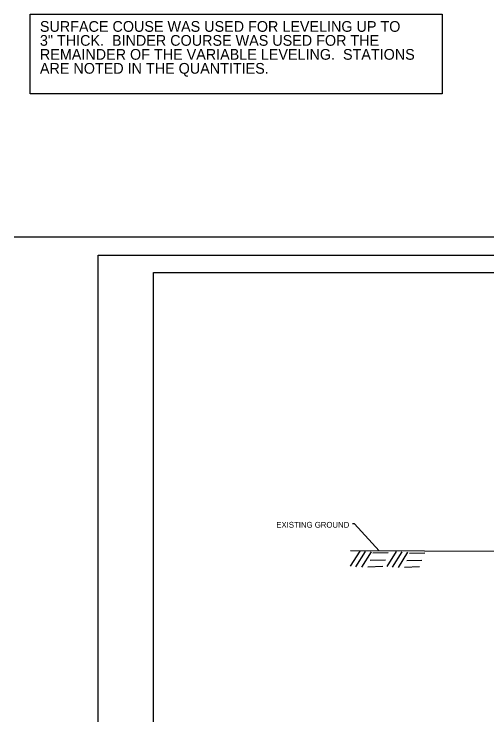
# Model space of a CAD drawing. Extents: x 1373719 to 1374161, y 379835 to 380167.
# Drawn here: x 1373870.4 to 1373923.2, y 380088.2 to 380166.6 of the extents above; entities that cross this region are included whole.
import ezdxf

# ---------------------------------------------------------------- set-up
doc = ezdxf.new("R2010")
doc.units = 0
for name, color, linetype in [('_30% NOTES', 7, 'Continuous'), ('DATE', 7, 'Continuous'), ('GREEN_TXT', 7, 'Continuous'), ('Ground Hatch', 7, 'Continuous'), ('R_NoPlot', 7, 'Continuous'), ('T_Drafting', 7, 'Continuous')]:
    doc.layers.add(name, color=color, linetype=linetype)

msp = doc.modelspace()

# ---------------------------------------------------------------- linework, layer by layer
at = {"layer": '_30% NOTES'}
msp.add_lwpolyline([(1373872.154, 380166.6), (1373918.243, 380166.6), (1373918.243, 380157.676), (1373872.154, 380157.676)], close=True, dxfattribs=at)
at = {"layer": 'DATE'}
for p, q in [((1374046.363, 380141.63), (1373870.363, 380141.63)), ((1373885.973, 380137.69), (1374044.063, 380137.69)), ((1373885.973, 380034.96), (1373885.973, 380137.69))]:
    msp.add_line(p, q, dxfattribs=at)
at = {"layer": 'GREEN_TXT'}
msp.add_lwpolyline([(1373911.198, 380106.549), (1373908.432, 380109.576), (1373908.188, 380109.579)], dxfattribs=at)
at = {"layer": 'Ground Hatch'}
for p, q in [((1373907.979, 380104.814), (1373909.046, 380106.521)), ((1373912.07, 380104.776), (1373913.138, 380106.483)), ((1373908.579, 380104.765), (1373909.646, 380106.473)), ((1373909.248, 380104.719), (1373910.315, 380106.426)), ((1373910.486, 380106.307), (1373912.182, 380106.352)), ((1373912.67, 380104.727), (1373913.738, 380106.435)), ((1373913.34, 380104.681), (1373914.407, 380106.388)), ((1373914.578, 380106.269), (1373916.274, 380106.315)), ((1373910.181, 380105.489), (1373911.877, 380105.535)), ((1373914.273, 380105.451), (1373915.969, 380105.496)), ((1373909.914, 380104.77), (1373911.61, 380104.815)), ((1373914.006, 380104.732), (1373915.702, 380104.777))]:
    msp.add_line(p, q, dxfattribs=at)
at = {"layer": 'R_NoPlot'}
msp.add_lwpolyline([(1373879.769, 380139.637), (1374046.439, 380139.637), (1374046.439, 380032.969), (1373879.769, 380032.969)], close=True, dxfattribs=at)
at = {"layer": 'T_Drafting'}
msp.add_lwpolyline([(1373907.987, 380106.564), (1373924.533, 380106.487), (1373943.45, 380108.654), (1373953.585, 380112.614), (1373955.026, 380112.615), (1373964.851, 380112.903), (1373975.028, 380112.689), (1373976.603, 380112.615), (1373985.688, 380110.353), (1373993.989, 380112.909), (1374008.917, 380113.95), (1374025.023, 380113.95)], dxfattribs=at)

# ---------------------------------------------------------------- texts
at = {"layer": '_30% NOTES'}
for s, p in [('SURFACE COUSE WAS USED FOR LEVELING UP TO ', (1373873.256, 380164.609)), ('3" THICK.  BINDER COURSE WAS USED FOR THE ', (1373873.256, 380163.047)), ('REMAINDER OF THE VARIABLE LEVELING.  STATIONS', (1373873.256, 380161.485)), ('ARE NOTED IN THE QUANTITIES. ', (1373873.256, 380159.922))]:
    msp.add_text(s, height=1.2, dxfattribs=at).set_placement(p)
at = {"layer": 'GREEN_TXT'}
msp.add_text('EXISTING GROUND', height=0.65, rotation=359.98, dxfattribs=at).set_placement((1373899.683, 380109.132))

doc.saveas('drawing.dxf')
